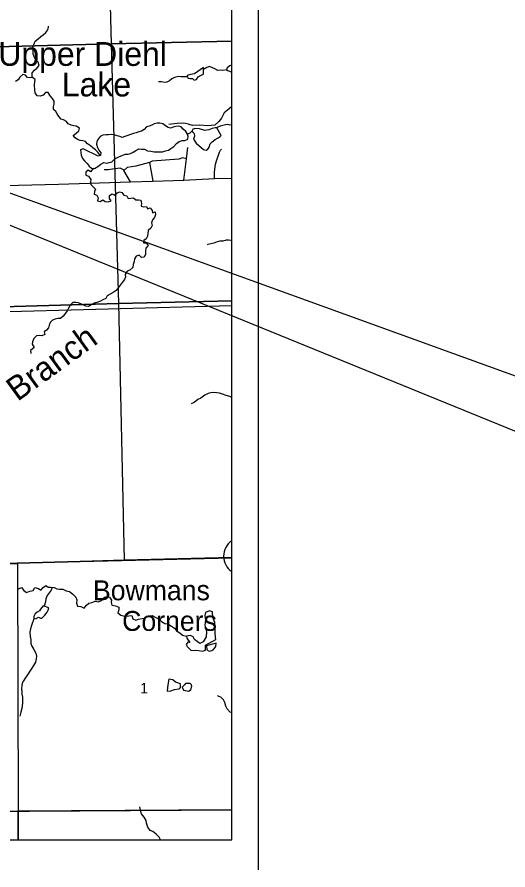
# Model space of a CAD drawing. Extents: x 0 to 34, y 0 to 22.
# Drawn here: x 8.938 to 10.885, y 13.887 to 17.274 of the extents above; entities that cross this region are included whole.
import ezdxf

# ---------------------------------------------------------------- set-up
doc = ezdxf.new("R2010")
doc.units = 0
for name, color, linetype in [('GM_X_Corporation', 7, 'Continuous'), ('GM_X_County_Road', 7, 'Continuous'), ('GM_X_Minor_Lake', 7, 'Continuous'), ('GM_X_Minor_Lake_Text', 7, 'Continuous'), ('GM_X_Minor_River', 7, 'Continuous'), ('GM_X_Minor_River_Text', 7, 'Continuous'), ('GM_X_Section_Text', 7, 'Continuous'), ('GM_X_Township_Road', 7, 'Continuous'), ('GM_X_Unincorporated', 7, 'Continuous'), ('GM_X_Unincorporated_Text', 7, 'Continuous'), ('SH_Data', 7, 'Continuous'), ('SH_Text', 7, 'Continuous')]:
    doc.layers.add(name, color=color, linetype=linetype)

msp = doc.modelspace()

# ---------------------------------------------------------------- linework, layer by layer
at = {"layer": 'GM_X_Corporation'}
msp.add_lwpolyline([(7.283, 17.3071), (7.2872, 17.1772), (7.2911, 17.0516), (7.2943, 16.935), (7.2998, 16.7507), (7.3046, 16.5913), (7.3049, 16.5704), (7.3097, 16.0633), (7.3129, 15.9614), (7.3375, 15.0689), (8.3803, 15.0917), (8.8365, 15.1033), (9.7895, 15.1275), (9.7895, 20.2375)], dxfattribs=at)
for points in [[(9.2853, 18.1891), (9.3117, 17.1675), (8.3006, 17.1406), (8.2786, 18.1687)], [(9.7895, 17.178), (9.7895, 18.2006), (9.2853, 18.1891), (9.3117, 17.1675)], [(9.7895, 16.1475), (9.7895, 17.178), (9.3117, 17.1675), (9.3404, 16.1359)], [(9.3117, 17.1675), (9.3404, 16.1359), (8.3266, 16.1074), (8.3006, 17.1406)], [(8.3266, 16.1074), (9.3404, 16.1359), (9.3634, 15.1175), (8.9404, 15.1037), (8.3505, 15.0912)], [(9.7895, 15.1273), (9.7895, 16.1475), (9.3404, 16.1359), (9.3634, 15.1175)], [(3.7367, 14.0069), (9.7895, 14.0069), (9.7895, 15.1275), (8.8365, 15.1033), (8.3803, 15.0917), (7.3375, 15.0689), (7.3134, 15.0684), (6.0746, 15.0468), (5.7825, 15.0418), (5.1362, 15.0301), (3.7218, 15.0051), (3.7359, 14.0555)], [(8.9404, 15.1037), (8.9421, 14.1205), (7.8527, 14.1143), (7.8364, 15.0804), (8.3505, 15.0912)], [(9.7895, 14.126), (9.7895, 15.1273), (9.3634, 15.1175), (8.9404, 15.1037), (8.9421, 14.1205)], [(8.9421, 14.0069), (9.7895, 14.0069), (9.7895, 14.126), (8.9421, 14.1205)], [(7.8543, 14.0069), (8.9421, 14.0069), (8.9421, 14.1205), (7.8527, 14.1143)]]:
    msp.add_lwpolyline(points, close=True, dxfattribs=at)
at = {"layer": 'GM_X_County_Road'}
msp.add_line((8.8367, 15.1028), (9.7895, 15.1269), dxfattribs=at)
for points in [[(7.3051, 16.5699), (8.9434, 16.6067), (9.1022, 16.6101), (9.3888, 16.6198), (9.477, 16.6223), (9.5999, 16.6258), (9.7209, 16.6324), (9.7895, 16.6343)], [(9.7895, 16.1277), (8.8082, 16.1011), (7.3099, 16.0628)], [(7.332, 14.1088), (8.3836, 14.1171), (9.7895, 14.1254)]]:
    msp.add_lwpolyline(points, dxfattribs=at)
at = {"layer": 'GM_X_Minor_Lake'}
for points in [[(9.6776, 17.0741), (9.6641, 17.0645), (9.6554, 17.0571), (9.6415, 17.0486), (9.626, 17.0461), (9.6124, 17.0414), (9.6159, 17.0316), (9.6231, 17.0294), (9.6345, 17.0299), (9.6403, 17.0228), (9.6501, 17.0255), (9.6568, 17.0363), (9.6689, 17.0425), (9.6776, 17.0468)], [(9.6776, 17.0468), (9.6776, 17.0741)], [(9.7895, 17.0831), (9.7819, 17.0807), (9.7718, 17.0726), (9.7692, 17.0631), (9.7803, 17.059), (9.7895, 17.0535)], [(9.2003, 16.7508), (9.2003, 16.7504), (9.1905, 16.7468), (9.191, 16.7362), (9.1923, 16.7256), (9.1974, 16.7124), (9.2063, 16.7026), (9.2159, 16.6921), (9.224, 16.682), (9.2336, 16.6738), (9.2457, 16.6728), (9.2581, 16.6809), (9.2704, 16.6902), (9.2825, 16.6957), (9.2942, 16.6939), (9.304, 16.696), (9.3142, 16.6991), (9.3243, 16.7092), (9.3345, 16.7142), (9.3442, 16.72), (9.3551, 16.7247), (9.3676, 16.7291), (9.3785, 16.7292), (9.3883, 16.7324), (9.3985, 16.7379), (9.4097, 16.7445), (9.4214, 16.7499), (9.4313, 16.7497), (9.4438, 16.7491), (9.4552, 16.7432), (9.4685, 16.7407), (9.4818, 16.7386), (9.4943, 16.738), (9.5041, 16.7389), (9.5155, 16.7387), (9.5271, 16.7422), (9.5385, 16.7447), (9.5486, 16.752), (9.5602, 16.7601), (9.5706, 16.772), (9.5811, 16.7798), (9.5936, 16.7837), (9.6038, 16.7835), (9.6162, 16.7886), (9.6164, 16.7992), (9.6148, 16.8094), (9.6071, 16.8196), (9.5967, 16.8282), (9.5894, 16.838), (9.5795, 16.8409), (9.5682, 16.8388), (9.5572, 16.836), (9.5471, 16.8328), (9.5376, 16.8357), (9.5269, 16.8421), (9.5165, 16.8499), (9.5048, 16.852), (9.4938, 16.8526), (9.4825, 16.8498), (9.4723, 16.844), (9.4618, 16.84), (9.4512, 16.838), (9.4427, 16.8276), (9.4325, 16.8211), (9.4212, 16.8175), (9.4103, 16.8147), (9.4001, 16.8111), (9.3888, 16.8076), (9.3775, 16.8036), (9.3654, 16.7993), (9.3557, 16.7957), (9.3458, 16.7998), (9.3347, 16.8023), (9.3237, 16.8063), (9.3116, 16.8069), (9.301, 16.806), (9.2908, 16.8055), (9.279, 16.8053), (9.2674, 16.7999), (9.26, 16.7891), (9.2552, 16.7796), (9.2538, 16.7686), (9.2578, 16.7553), (9.2632, 16.7452), (9.2702, 16.7342), (9.2692, 16.724), (9.2594, 16.7219)], [(9.7307, 16.8345), (9.7235, 16.8333), (9.7121, 16.8316), (9.699, 16.8258), (9.6824, 16.8233), (9.6618, 16.8298), (9.6433, 16.8307), (9.6335, 16.8268), (9.6324, 16.8226), (9.6343, 16.8184), (9.6401, 16.8117), (9.6414, 16.8003), (9.6382, 16.7893), (9.6482, 16.7735), (9.6781, 16.7477), (9.688, 16.7455), (9.6951, 16.749), (9.6999, 16.7574), (9.7047, 16.77), (9.7125, 16.7789), (9.7237, 16.7881), (9.7354, 16.794), (9.7444, 16.799), (9.7481, 16.8036)], [(9.7481, 16.8036), (9.7307, 16.8345)], [(9.2594, 16.7219), (9.2003, 16.7508)], [(9.0424, 14.9356), (9.0313, 14.9221), (9.0268, 14.9163), (9.0178, 14.9105), (9.0107, 14.9046), (9.0055, 14.8935), (9.0049, 14.8848), (9.0136, 14.8857), (9.0231, 14.8908), (9.0307, 14.8864), (9.0372, 14.8865), (9.0487, 14.8988), (9.0576, 14.9107), (9.0613, 14.9191), (9.0642, 14.9275)], [(9.0642, 14.9275), (9.0424, 14.9356)], [(9.7268, 14.802), (9.7248, 14.8122), (9.7241, 14.8289), (9.7245, 14.8502), (9.7223, 14.8699), (9.7151, 14.8899), (9.7136, 14.9127), (9.7014, 14.9167), (9.6852, 14.9092), (9.6835, 14.897), (9.6857, 14.8784), (9.6826, 14.8586), (9.6899, 14.8333), (9.6887, 14.8124), (9.6769, 14.7928), (9.6629, 14.7858), (9.6422, 14.8029), (9.6363, 14.813), (9.626, 14.8186), (9.6101, 14.8153), (9.6121, 14.8081), (9.6238, 14.7908), (9.6154, 14.7922), (9.6095, 14.7818), (9.6126, 14.7751), (9.6292, 14.7582), (9.6444, 14.76), (9.6592, 14.7583), (9.6744, 14.7556), (9.6854, 14.7603), (9.6851, 14.78)], [(9.6851, 14.78), (9.7268, 14.802)], [(9.6893, 14.7771), (9.6914, 14.7608), (9.7006, 14.7556), (9.7105, 14.758), (9.7161, 14.7619), (9.7224, 14.7693), (9.7261, 14.775), (9.7278, 14.7872)], [(9.7278, 14.7872), (9.6893, 14.7771)], [(9.587, 14.6261), (9.5671, 14.633), (9.5567, 14.6423), (9.5408, 14.6444), (9.5376, 14.6299), (9.5345, 14.612), (9.5336, 14.5971), (9.5476, 14.5985), (9.5631, 14.6033), (9.5793, 14.607)], [(9.587, 14.6261), (9.5671, 14.633), (9.5567, 14.6423), (9.5408, 14.6444), (9.5376, 14.6299), (9.5345, 14.612), (9.5336, 14.5971), (9.5476, 14.5985), (9.5631, 14.6033), (9.5793, 14.607)], [(9.5793, 14.607), (9.5834, 14.6094), (9.5861, 14.6119), (9.587, 14.6261)], [(9.6019, 14.6226), (9.5933, 14.6126), (9.5988, 14.6016), (9.619, 14.5978), (9.6272, 14.6036), (9.6316, 14.617), (9.6303, 14.6223), (9.6249, 14.6279)], [(9.6249, 14.6279), (9.6118, 14.6281), (9.6066, 14.6273), (9.6019, 14.6226)]]:
    msp.add_lwpolyline(points, dxfattribs=at)
at = {"layer": 'GM_X_Minor_River'}
for points in [[(8.9976, 17.0331), (8.9985, 17.0517), (9.0078, 17.0628), (9.0186, 17.0717), (9.0261, 17.0817), (9.0217, 17.0942), (9.011, 17.1054), (9.0059, 17.1163), (9.0023, 17.1265), (9.0018, 17.1368), (9.0017, 17.1466), (9.0012, 17.1565), (9.0056, 17.1676), (9.0107, 17.1775), (9.0219, 17.1875), (9.032, 17.1972), (9.0422, 17.2026), (9.0522, 17.2126), (9.06, 17.2233), (9.0629, 17.234), (9.0629, 17.2374)], [(9.7695, 17.0641), (9.7541, 17.0618), (9.7442, 17.0624), (9.7343, 17.0611), (9.7225, 17.0678), (9.7019, 17.0778), (9.6913, 17.0728), (9.6776, 17.0661)], [(9.2682, 16.7238), (9.2592, 16.7367), (9.25, 16.7465), (9.2392, 16.7547), (9.2293, 16.7625), (9.2175, 16.77), (9.2094, 16.7797), (9.1995, 16.7826), (9.1889, 16.784), (9.1778, 16.788), (9.1683, 16.794), (9.1613, 16.8041), (9.1729, 16.813), (9.1834, 16.8223), (9.1859, 16.8326), (9.1729, 16.8407), (9.1634, 16.8425), (9.1524, 16.845), (9.1414, 16.8494), (9.1341, 16.8592), (9.123, 16.8659), (9.1131, 16.8688), (9.1035, 16.8785), (9.098, 16.8891), (9.0926, 16.8989), (9.083, 16.9071), (9.0825, 16.9173), (9.0854, 16.9295), (9.0856, 16.9398), (9.079, 16.9499), (9.0694, 16.9608), (9.0616, 16.9744), (9.051, 16.9738), (9.0417, 16.9631), (9.03, 16.9599), (9.0187, 16.9613), (9.0102, 16.9729), (9.0089, 16.9831), (9.0078, 17.0044), (9.0088, 17.0162), (9.0098, 17.0261), (9.0002, 17.0331), (8.9896, 17.033), (8.9794, 17.0336), (8.9717, 17.0434), (8.9611, 17.0459), (8.9495, 17.0355), (8.9424, 17.0248), (8.9323, 17.0178)], [(9.614, 17.0369), (9.5999, 17.0359), (9.5893, 17.037), (9.579, 17.0372), (9.5624, 17.034), (9.5526, 17.0278), (9.5428, 17.02), (9.5326, 17.0146), (9.5227, 17.0145), (9.5117, 17.0159), (9.5022, 17.0161), (9.4992, 17.0161)], [(9.7895, 16.8477), (9.7841, 16.844), (9.7739, 16.8466), (9.7644, 16.8461), (9.7542, 16.8429), (9.7443, 16.8405), (9.7345, 16.837), (9.7307, 16.8344)], [(9.6327, 16.8219), (9.624, 16.8132), (9.6148, 16.8094)], [(9.2418, 16.6731), (9.23, 16.6589), (9.2204, 16.6664), (9.2107, 16.6575), (9.2116, 16.6465), (9.2215, 16.6414), (9.2304, 16.6293), (9.2302, 16.6187), (9.2303, 16.6084), (9.2403, 16.6002), (9.2499, 16.5905), (9.2455, 16.5806), (9.2441, 16.5699), (9.2548, 16.5663), (9.2602, 16.5565), (9.2573, 16.5443), (9.2684, 16.5414), (9.2781, 16.548), (9.2877, 16.542), (9.2998, 16.5399), (9.3111, 16.5435), (9.3049, 16.5537), (9.3047, 16.5658), (9.3149, 16.5712), (9.3244, 16.5668), (9.3342, 16.5742), (9.3443, 16.5796), (9.3538, 16.5767), (9.3615, 16.5666), (9.374, 16.5641), (9.3795, 16.5535), (9.3901, 16.554), (9.3999, 16.5553), (9.4099, 16.5482), (9.4197, 16.548), (9.4296, 16.5466), (9.4316, 16.5337), (9.431, 16.5231), (9.4405, 16.5198), (9.4515, 16.5218), (9.4558, 16.512), (9.466, 16.516), (9.4744, 16.5062), (9.4749, 16.4967), (9.4859, 16.501), (9.4868, 16.49), (9.4839, 16.4782), (9.4761, 16.4686), (9.4713, 16.4564), (9.4737, 16.4462), (9.4686, 16.4351), (9.4589, 16.4259), (9.4575, 16.4141), (9.4562, 16.4035), (9.4506, 16.3935), (9.4409, 16.3862), (9.4395, 16.3767), (9.4505, 16.3768), (9.4586, 16.3663), (9.4485, 16.3555), (9.4475, 16.3453), (9.4473, 16.3328), (9.4426, 16.3198), (9.432, 16.3185), (9.4224, 16.3282), (9.4107, 16.3247), (9.4037, 16.3143), (9.4023, 16.3029), (9.3983, 16.2907), (9.397, 16.2793), (9.3861, 16.2682), (9.3756, 16.2646), (9.3674, 16.2516), (9.368, 16.2421), (9.3639, 16.2311), (9.3554, 16.2203), (9.3476, 16.2092), (9.3387, 16.1985), (9.3309, 16.1881), (9.3189, 16.1796), (9.308, 16.1738), (9.2963, 16.1668), (9.2908, 16.1564), (9.2791, 16.151), (9.2694, 16.1459), (9.2551, 16.14), (9.2445, 16.1372), (9.2325, 16.131), (9.2216, 16.124), (9.2114, 16.1254), (9.2011, 16.131), (9.1911, 16.1354), (9.1809, 16.1387), (9.171, 16.14), (9.1589, 16.1403), (9.1496, 16.1299), (9.1426, 16.1173), (9.1366, 16.1073), (9.13, 16.0977), (9.1207, 16.0855), (9.1102, 16.077)], [(9.7895, 16.3858), (9.7877, 16.3863), (9.7774, 16.3884), (9.7672, 16.3875), (9.7548, 16.3843), (9.7427, 16.3834), (9.7313, 16.381), (9.7185, 16.3762), (9.7072, 16.3731), (9.6955, 16.3706), (9.6918, 16.3691)], [(9.1102, 16.077), (9.0996, 16.0765), (9.089, 16.0744), (9.0792, 16.0705), (9.0692, 16.0609), (9.0651, 16.0498), (9.0634, 16.0399), (9.0556, 16.0303), (9.0454, 16.0237), (9.0479, 16.0131), (9.037, 16.0081), (9.0256, 16.0094), (9.0158, 16.0074), (9.0053, 15.9978), (8.999, 15.9848), (8.9984, 15.9745), (9.0062, 15.9613), (8.992, 15.9498), (8.9929, 15.9399), (8.9933, 15.9373)], [(9.7895, 15.7635), (9.7819, 15.7665), (9.7677, 15.7712), (9.7536, 15.7767), (9.741, 15.7803), (9.7304, 15.782), (9.7178, 15.7826), (9.7065, 15.7816), (9.6962, 15.7796), (9.6835, 15.7718), (9.6677, 15.7609), (9.6553, 15.7546), (9.6403, 15.7433), (9.6282, 15.7378)], [(8.9419, 15.0015), (8.9562, 15.009), (8.9647, 14.9973), (8.9759, 14.9892), (8.9895, 14.9943), (9.0016, 14.9972), (9.0089, 15.0091), (9.0231, 15.0051), (9.0327, 14.9984), (9.042, 15.0092), (9.0521, 15.0162), (9.0617, 15.0096), (9.0712, 15.0097), (9.086, 15.0088), (9.096, 15.0037), (9.1062, 15.0019), (9.1195, 15.0018), (9.1326, 14.9955), (9.1459, 14.9931), (9.1601, 14.9823), (9.1713, 14.9703), (9.1757, 14.9598), (9.174, 14.9464), (9.1784, 14.934), (9.1909, 14.933), (9.2047, 14.9272), (9.2128, 14.9379), (9.2226, 14.9472), (9.2354, 14.9493), (9.2475, 14.9541), (9.2608, 14.9516), (9.2736, 14.9572), (9.2848, 14.9699), (9.2954, 14.9731), (9.3049, 14.9702), (9.3123, 14.9589), (9.311, 14.949), (9.3146, 14.9385), (9.3283, 14.9357), (9.3413, 14.9313), (9.3414, 14.9203), (9.3379, 14.9077), (9.3494, 14.8992), (9.3593, 14.8967), (9.3688, 14.8953), (9.3817, 14.8963), (9.3931, 14.8972), (9.3975, 14.884), (9.4097, 14.8785), (9.4195, 14.8828), (9.4339, 14.8853), (9.4441, 14.887), (9.4607, 14.8968), (9.4739, 14.8974), (9.4889, 14.8893), (9.5023, 14.883), (9.5115, 14.8733), (9.5242, 14.8663), (9.5367, 14.865), (9.5509, 14.855), (9.5621, 14.8472), (9.571, 14.8371), (9.5844, 14.8289), (9.5948, 14.8192), (9.6101, 14.8153)], [(9.0781, 15.0093), (9.074, 14.9984), (9.0651, 14.988), (9.0577, 14.9764), (9.0518, 14.9631), (9.0509, 14.952), (9.0456, 14.9344)], [(9.0049, 14.8848), (8.9951, 14.8584), (8.9919, 14.8451), (8.9895, 14.831), (8.9898, 14.8139), (8.9934, 14.801), (8.9933, 14.7862), (8.9969, 14.7764), (9.0054, 14.7625), (9.0129, 14.7474), (9.0154, 14.7357), (9.0144, 14.7254), (9.0108, 14.7128), (9.0038, 14.6994), (8.9968, 14.6891), (8.9894, 14.6772), (8.9798, 14.6622), (8.9705, 14.6484), (8.9638, 14.6384), (8.9591, 14.6288), (8.9569, 14.6193), (8.956, 14.6063), (8.957, 14.595), (8.9579, 14.5847), (8.96, 14.5737), (8.9602, 14.5616), (8.96, 14.5498), (8.959, 14.5403), (8.9573, 14.5285), (8.9537, 14.5136), (8.9487, 14.4976)], [(9.7895, 14.5109), (9.7829, 14.5131), (9.7712, 14.5266), (9.7665, 14.5379), (9.7628, 14.5526), (9.7577, 14.5632), (9.7462, 14.5736), (9.7328, 14.5784)], [(9.5072, 14.0069), (9.5014, 14.0174), (9.4894, 14.0297), (9.4767, 14.0405), (9.4664, 14.0438), (9.4571, 14.0573), (9.4519, 14.0735), (9.4506, 14.0834), (9.4428, 14.0966), (9.4319, 14.1101), (9.4282, 14.1252), (9.4254, 14.1384)]]:
    msp.add_lwpolyline(points, dxfattribs=at)
at = {"layer": 'GM_X_Township_Road'}
msp.add_line((9.4635, 16.6964), (9.477, 16.6223), dxfattribs=at)
for points in [[(9.7895, 16.9191), (9.7795, 16.9096), (9.7594, 16.8938), (9.7491, 16.8718), (9.7384, 16.8593), (9.7226, 16.8444), (9.6938, 16.8417), (9.663, 16.8445), (9.6345, 16.8429), (9.6208, 16.8475)], [(9.6208, 16.8475), (9.6188, 16.8482), (9.6001, 16.8518), (9.5739, 16.851), (9.5399, 16.8469)], [(9.5999, 16.6258), (9.6105, 16.7108), (9.6162, 16.756)], [(9.7209, 16.6324), (9.7209, 16.657), (9.7223, 16.6702), (9.7257, 16.6892), (9.7305, 16.7064), (9.7376, 16.7252), (9.7413, 16.7368), (9.7455, 16.745), (9.7492, 16.7495)], [(9.6105, 16.7108), (9.5939, 16.7143), (9.5796, 16.7089), (9.4739, 16.7012), (9.4635, 16.6964), (9.4092, 16.6814), (9.3748, 16.6769), (9.3624, 16.665)], [(9.3888, 16.6198), (9.3624, 16.665), (9.3611, 16.6674), (9.3476, 16.6738), (9.3169, 16.6702), (9.3011, 16.6667), (9.284, 16.6673)]]:
    msp.add_lwpolyline(points, dxfattribs=at)
at = {"layer": 'GM_X_Unincorporated'}
msp.add_line((9.7895, 15.0718), (9.7895, 15.1938), dxfattribs=at)
msp.add_arc((9.8321, 15.1328), 0.0744, 124.9145, 235.0855, dxfattribs=at)
at = {"layer": 'SH_Data'}
msp.add_line((9.8945, 20.8873), (9.8945, 13.8873), dxfattribs=at)
at = {"layer": 'SH_Text'}
msp.add_lwpolyline([(11.7478, 15.5458), (6.1293, 17.5829), (11.7478, 15.2891)], close=True, dxfattribs=at)

# ---------------------------------------------------------------- texts
at = {"layer": 'GM_X_Minor_Lake_Text'}
for s, height, rotation, p in [('Upper Diehl', 0.094732, 359.9569, (8.8639, 17.0802)), ('Lake', 0.09473, 359.9568, (9.1158, 16.9587))]:
    msp.add_text(s, height=height, rotation=rotation, dxfattribs=at).set_placement(p)
at = {"layer": 'GM_X_Minor_River_Text'}
msp.add_text('Branch', height=0.09473, rotation=35.9921, dxfattribs=at).set_placement((8.9401, 15.7452))
at = {"layer": 'GM_X_Section_Text'}
msp.add_text('1', height=0.0419, rotation=0, dxfattribs=at).set_placement((9.4268, 14.5882))
at = {"layer": 'GM_X_Unincorporated_Text'}
for s, p in [('Bowmans', (9.2393, 14.9581)), ('Corners', (9.3552, 14.8365))]:
    msp.add_text(s, height=0.07898, rotation=0, dxfattribs=at).set_placement(p)

doc.saveas('drawing.dxf')
